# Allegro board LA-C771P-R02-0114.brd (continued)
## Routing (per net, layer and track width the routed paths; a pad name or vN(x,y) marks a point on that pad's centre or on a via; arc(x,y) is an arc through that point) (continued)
DDR_A_ODT2: length 59.6
  IN2 w0.102: 108.21,61.86 108.21,62.72 106.28,64.65 106.28,69.57 106.28,69.64 105.05,70.86 104.45,70.86 v3(103.85,70.26)
  IN2 w0.203: 108.21,61.86 108.21,59.37 113.36,54.21 114.85,54.21 116.25,52.81 116.25,46.77 114.5,45.02 114.5,42.08 114.29,41.86 113.38,41.86 113.1,41.58 113.1,37.4 112.84,37.14 112.33,37.14 112.04,37.43 112.04,39.18 111.81,39.42 111.34,39.42 111.04,39.13 111.04,37.55 110.81,37.32 110.43,37.32 110.22,37.52 110.22,40.62 109.79,41.05 107.4,41.05 106.36,40.01 v3(105.8,40.01)
  BOTTOM w0.102: UC4.P42 v3(103.85,70.26)
  BOTTOM w0.165: JDIMM1.120 105.23,39.44 v3(105.8,40.01)
DDR_A_RAS#: length 44.4
  IN2 w0.102: 104.85,63.21 104.85,64.44 105.26,64.85 105.26,67.22 105.18,67.29 105.18,67.3 104.96,67.52 104.96,67.52 104.95,67.53 104.6,67.53 104.43,67.71 104.43,68.05 104.24,68.23 v3(102.84,68.23)
  IN2 w0.203: v3(102.22,41.25) 101.89,41.25 101.66,41.48 101.66,42.01 101.39,42.29 101.39,42.58 101.59,42.78 102.33,42.78 102.49,42.62 102.49,42.21 102.69,42.01 103.04,42.01 103.3,42.27 103.3,42.97 103.5,43.17 103.85,43.17 104.22,42.8 104.88,42.8 105.09,43.01 105.09,44.62 105.37,44.9 105.37,46.79 106.48,47.9 106.48,53.9 106.76,54.18 107.09,54.18 107.29,53.98 107.29,52.68 107.5,52.47 107.79,52.47 108.1,52.78 108.1,55.14 104.85,58.39 104.85,63.21
  BOTTOM w0.102: UC4.M45 v3(102.84,68.23)
  BOTTOM w0.165: v3(102.22,41.25) 102.23,41.24 JDIMM1.110
DDR_A_RST#: length 81.1
  TOP w0.102: v3(75.32,42.22) 74.71,41.61 74.71,39.81 CD2.1 73.85,38.34 75.01,37.17 v3(75.83,37.17) ; CC20.1 104.08,71.1 v3(103.83,70.85)
  IN2 w0.102: 95.15,76.26 97.44,76.26 98.48,75.22 98.48,74.83 99.86,73.44 101.09,73.44 101.53,73 101.53,72.19 101.65,72.07 102.83,72.07 103.15,71.74 103.15,71.39 103.7,70.85 v3(103.83,70.85)
  IN2 w0.127: v3(75.32,42.22) 75.24,42.3 75.24,45.06 68.36,51.95 68.36,59.44 67.2,60.6 67.2,65.93 77.2,75.92 93.39,75.92 93.72,76.26 95.15,76.26
  BOTTOM w0.102: UC4.P41 v3(103.83,70.85) ; JDIMM1.30 v3(75.83,37.17)
DDR_A_WE#: length 51.4
  IN2 w0.203: v3(104.1,48.16) 104.1,48.19 103.77,48.52 103.43,48.52 103.18,48.27 v3(103.18,45.19)
  BOTTOM w0.102: 97.82,62.36 97.95,62.49 99.96,62.49 101.3,63.83 101.3,64.43 101.36,64.49 101.36,65.46 UC4.H51
  BOTTOM w0.165: v3(104.1,48.16) 103.87,48.39 103.41,48.39 103.08,48.06 101.47,48.06 100.93,48.6 100.93,50.48 101.63,51.17 101.63,53.5 101.44,53.69 101.16,53.69 100.97,53.5 100.97,51.78 100.78,51.58 100.5,51.58 100.31,51.78 100.31,55.37 100.12,55.57 99.84,55.57 99.65,55.37 99.65,48.56 99.46,48.37 99.18,48.37 98.99,48.56 98.99,55.82 96.35,58.46 96.35,60.89 97.82,62.36 ; JDIMM1.113 103.13,45.37 103.18,45.32 v3(103.18,45.19)
DDR_CORE_PWROK: length 61.1
  TOP w0.102: v3(100.54,74.38) 100.4,74.24 92.33,74.24 90.56,76 87.79,76 85.77,78.02 85.77,78.92 85.45,79.24 83.4,79.24 81.77,80.87 81.77,83.02 83.42,84.66 84.92,84.66 86.77,86.52 93.25,86.52 v2(94.13,87.4) 94.65,87.91 v3(94.65,92.72)
  IN2 w0.102: v3(108.69,70.55) 108.69,70.55 108.03,69.88 107.53,69.88 107.36,70.05 107.02,70.39 106.22,70.39 105.31,71.3 105.31,72.9 104.2,74.02 102.77,74.02 102.27,74.53 100.69,74.53 v3(100.54,74.38)
  BOTTOM w0.102: v3(108.69,70.55) 108.69,70.55 108.65,70.54 108.2,70.1 UC4.AB42 ; RC43.2 90.63,93.63 CC21.1 91.72,93.7 UC9.4 94.17,93.7 94.65,93.23 v3(94.65,92.72)
DDR_PWROK: length 81.6
  TOP w0.102: v3(108.69,69.95) 108.14,70.49 108.14,72.01 CC94.1
  TOP w0.254: v3(156.28,28.65) 157.32,28.65 157.61,28.36 v2(157.61,28.1) 157.61,27.97 157.35,27.71 PR406.2
  IN2 w0.127: v3(156.28,28.65) 155.61,29.31 155.61,37.6 154.11,39.1 154.11,41.46 151.01,44.56 145.55,44.56 142.17,47.94 134.05,47.94 119.15,62.84 119.15,64.23 118.49,64.89 117.88,64.89 116.81,65.96 116.81,66.21 116.57,66.45 115.73,66.45 114.73,67.45 114.36,67.45 113.41,68.39 112.26,68.39 112.17,68.3 111.7,68.3 111.14,68.86 111.14,69.54 110.74,69.94 108.69,69.94 v3(108.69,69.95)
  BOTTOM w0.102: UC4.AD42 109.07,69.94 108.69,69.94 v3(108.69,69.95)
  BOTTOM w0.203: v3(156.28,28.65) 155.76,29.16 155.76,30.47 155.58,30.65 PU303.10
DDR_RCOMP0: length 2.9
  TOP w0.254: v3(108.7,69.36) 108.98,69.36 v2(109.35,69.73) 109.35,71.05 RC3.2
  BOTTOM w0.254: UC4.AD44 108.95,69.12 v3(108.7,69.36)
DDR_RCOMP1: length 6.2
  TOP w0.254: RC4.2 112.94,69.86 113.34,69.45 v2(113.34,68.97) 113.34,68.69 112.81,68.16 110.71,68.16 v3(110.6,68.05)
  BOTTOM w0.254: UC4.AF45 110.25,68.41 v3(110.6,68.05)
DDR_RCOMP2: length 4.4
  TOP w0.254: v3(108.76,68.05) 109.1,68.05 109.79,68.74 109.79,70.52 RC5.2
  BOTTOM w0.381: v3(108.76,68.05) 109.12,68.41 UC4.AD45
DDR_TERMN0: length 2.5
  TOP w0.254: v3(110.6,69.47) 110.6,70.25 111.21,70.85 RC1.2
  BOTTOM w0.254: UC4.AF42 110.25,69.83 v3(110.6,69.47)
DDR_TERMN1: length 2.6
  TOP w0.254: v3(111.74,69.47) 112.09,69.81 RC2.2
  BOTTOM w0.254: UC4.AH42 111.1,69.79 111.42,69.47 v3(111.74,69.47)
DEVSLP_SOC: length 1.1
  TOP w0.102: T3.1 116.72,83.85 v3(117.13,84.26)
  BOTTOM w0.102: v3(117.13,84.26) 116.98,84.11 UC4.AY14
DH_CHG: length 1.5
  TOP w0.102: PR217.1 194.09,72.02 v2(194.8,72.73)
  vias: v3(193.35,71.29) v3(194.01,71.28) v3(196.82,71.45) v3(197.42,71.45)
DISPOFF#: length 17.4
  BOTTOM w0.102: JEDP1.10 58.9,97.04 58.38,96.53 54.8,96.53 53.53,95.26 52.61,95.26 51.29,93.94 RX6.2 51.02,94.05 51.02,94.69 v2(50.81,94.9) 50.2,94.9 49.29,93.99 RX8.2 CX14.2 49.28,92.64 RX7.2
DL_CHG: length 4.9
  TOP w0.102: v3(196.69,69.73) v2(196.69,68.84)
  IN2 w1.016: 193.26,66.18 196.12,69.03
  vias: v3(191.68,66.49) v3(191.68,65.85) v3(197.29,69.73)
DRAM_VDD_S4_CLK: length 25.8
  TOP w0.102: v3(122.79,63.89) v2(122.79,63.28)
  TOP w0.381: CC29.1 109.46,71.98 v3(109.65,71.78)
  IN2 w0.254: v3(109.65,71.78) 109.91,72.04 112.32,72.04 112.6,72.32 116.6,72.32 116.82,72.09 118.27,72.09 119.62,70.75 119.62,70.29 120.02,69.88 120.51,69.88 121.11,69.27 121.11,66.22 122.79,64.55 v3(122.79,63.89)
  BOTTOM w0.254: UC4.AF38 110.01,72.14 v3(109.65,71.78) 109.29,72.14 UC4.AD38
  BOTTOM w0.381: RC69.1 121.57,60.49 CC30.1 121.57,62.67 v3(122.79,63.89)
E51RXD_P80CLK: length 243.8
  TOP w0.102: v3(196.92,7.37) 190.83,13.47 175.2,13.47 v2(169.85,18.82) 169.13,19.54 v3(168.8,19.54) ; v3(67.93,24.95) 67.57,24.95 66.13,26.39 UB1.31 ; v3(167.47,82.61) 167.47,83.97 163.42,88.02 154.43,88.02 152.64,89.81 152.64,91.83 152.3,92.16 150.6,92.16 RM12.1
  BOTTOM w0.102: v3(67.93,24.95) 68.18,24.7 69.32,24.7 71.22,22.81 71.22,22.25 72.97,20.49 74.78,20.49 76.37,18.9 79.56,18.9 80.53,19.87 82.06,19.87 83.96,17.97 86.34,17.97 86.82,18.45 90.11,18.45 91.32,17.23 92.66,17.23 93.45,16.44 94.44,16.44 95.25,17.26 101.39,17.26 101.97,16.67 103.42,16.67 104.01,17.26 108.75,17.26 109.77,16.24 114.21,16.24 116.47,13.98 120.14,13.98 126.24,7.88 162.4,7.88 168.8,14.28 v3(168.8,19.54) 168.8,20.75 168.33,21.22 168.33,81.75 v3(167.47,82.61) ; JP1.3 v3(196.92,7.37)
E51TXD_P80DATA: length 242.1
  TOP w0.102: UB1.30 66.53,26.55 67.56,25.51 v3(67.65,25.51) ; v3(167.04,83.02) v2(167.04,83.7) 167.04,84.04 163.29,87.79 154.31,87.79 152.41,89.7 152.41,91.27 RM13.2 RM11.1 ; v3(168.36,20.05) 169.32,20.05 175.67,13.7 190.92,13.7 196.74,7.88 197.37,7.88 v3(197.78,7.46)
  BOTTOM w0.102: v3(167.04,83.02) 167.04,82.2 168.1,81.14 168.1,20.3 v3(168.36,20.05) 168.36,14.16 162.3,8.11 126.55,8.11 120.45,14.2 116.57,14.2 114.31,16.46 109.87,16.46 108.85,17.48 103.91,17.48 103.33,16.9 102.07,16.9 101.48,17.49 95.16,17.49 94.34,16.67 93.55,16.67 92.76,17.46 91.42,17.46 90.2,18.67 87.39,18.67 86.77,19.29 82.96,19.29 82.15,20.1 80.09,20.1 79.28,19.29 76.31,19.29 74.88,20.72 73.07,20.72 71.51,22.27 71.51,22.83 69.41,24.94 68.8,24.94 68.23,25.51 v3(67.65,25.51) ; JP1.2 198.17,7.08 v3(197.78,7.46)
EC_BKOFF#: length 112
  TOP w0.102: v3(74.31,19.97) 75.12,19.16 76.06,19.16 76.54,18.68 76.54,18.07 77.64,16.97 UB1.105 ; v3(44.51,52.73) 44.53,52.73 44.53,52.73 40.53,56.73 40.48,56.73 40.26,56.95 40.26,57 39.73,57.53 39.73,69.62 39.5,69.84 39.5,81.01 44.15,85.66 44.15,88.27 46.16,90.28 47.89,90.28 v3(48.93,91.32)
  IN2 w0.127: v3(74.31,19.97) 73.97,19.63 73.97,18.4 73.11,17.53 71.86,17.53 71.58,17.82 71.58,17.82 71.39,18 71.33,18.06 69.86,18.06 69.05,17.25 64.02,17.25 51.93,29.35 51.93,41.13 50.4,42.66 50.4,51.04 49.41,52.02 45.21,52.02 v3(44.51,52.73)
  BOTTOM w0.102: RX7.1 v3(48.93,91.32)
EC_CLEAR_CMOS: length 6.8
  TOP w0.102: v3(66.68,9.79) 66.93,10.03 UB1.68
  BOTTOM w0.102: v3(66.68,9.79) 65.35,9.79 v2(65.31,9.74) 65.26,9.69 RB31.2 65.54,8.75 66.12,8.16 QB1.2
EC_CS0#: length 35
  TOP w0.102: UB1.128 80.17,26.17 80.33,26.33 80.33,29.1 81.11,29.89 81.11,32.71 78.43,35.39 75.39,35.39 73.67,37.12 69.04,37.12 62.72,43.44 v2(60.54,43.44) RPC8.8
EC_ENVDD: length 97.7
  TOP w0.102: v3(70.16,22.99) 70.89,22.26 70.89,14.84 69.33,13.28 UB1.74 ; v3(76.43,85.93) 76.39,85.98 RX1.1
  IN2 w0.127: v3(62.17,35.95) 62.17,31.61 68.41,25.37 68.41,24.74 v3(70.16,22.99)
  BOTTOM w0.102: v3(76.43,85.93) 69.89,85.93 68.36,84.4 67.76,84.4 67.24,83.88 66.44,83.88 64.3,81.74 64.3,77.31 63.24,76.25 63.24,72.25 66.52,68.97 66.84,68.97 67.4,68.4 67.4,59.31 59.13,51.04 59.13,47.12 56.98,44.96 56.98,40.56 61.59,35.95 v3(62.17,35.95)
EC_KBRST#: length 103.8
  TOP w0.102: UB1.2 77.73,29.83 77.5,30.06 v3(77.5,30.06)
  BOTTOM w0.102: UC4.B18 98.02,82.02 97.61,82.02 96.82,82.81 96.82,82.89 95.91,83.8 95.02,83.8 94.8,84.02 94,84.02 93.17,84.84 90.24,84.84 89.6,85.48 RC36.1 89.49,84.85 89.14,84.5 89.14,84.03 88.76,83.65 86.23,83.65 85.19,82.61 73.61,82.61 72.95,81.95 70.89,81.95 68.11,79.17 68.11,72.14 68.66,71.58 68.66,70.38 69.71,69.33 69.71,58.39 61.43,50.1 61.43,46.13 60.21,44.91 60.21,38.84 62.73,36.32 62.73,35.18 63.89,34.02 64.52,34.02 64.92,33.61 68.87,33.61 71.2,31.28 v2(72.8,31.28) 76.28,31.28 v3(77.5,30.06)
EC_LID_OUT#: length 7.3
  BOTTOM w0.102: RC35.2 93.75,85.48 94.37,84.86 94.37,84.58 v1(94.52,84.42) 94.72,84.22 95.78,84.22 97.09,82.91 97.41,82.91 97.56,82.76 97.83,82.76 98.12,82.48 98.29,82.31 UC4.C17
EC_MUTE#: length 67
  TOP w0.102: v3(72.32,5.39) 72.22,5.49 72.22,7.04 RB12.1 73.94,8.77 73.94,10.29 72.93,11.3 UB1.83 ; RA12.1 31.1,28.46 RA10.2 32.09,28.46 32.79,27.76 33.37,27.76 35.72,25.41 v3(35.72,15.43)
  BOTTOM w0.102: v3(35.72,15.43) 35.72,14.94 37.6,13.06 37.6,10.8 41.82,6.58 59.83,6.58 60.46,5.95 62.72,5.95 63.76,4.91 69.63,4.91 70.62,5.9 71.81,5.9 v3(72.32,5.39)
EC_ON: length 185.1
  TOP w0.203: UB1.112 78.49,19.77 78.18,20.08
  TOP w0.254: v3(104.12,26.58) 104.32,26.37 104.32,13.65 v2(104.68,13.29) 105.21,12.76 v3(105.21,12.4) ; 78.18,20.08 77.28,20.99 74.3,20.99 v3(74.05,21.24)
  IN2 w0.254: v3(104.12,26.58) 103.2,25.66 96.57,25.66 96.31,25.93 93.87,25.93 92.71,27.09 89.47,27.09 88.09,25.71 86.06,25.71 85.2,24.85 81.06,24.85 79.26,23.05 77.75,23.05 76.34,21.65 74.45,21.65 v3(74.05,21.24) ; v3(194.25,43.56) 194.3,43.56 194.95,42.91 201.96,42.91 203.05,41.81 203.05,31.15 179.17,7.27 128.47,7.27 124.28,11.46 110.01,11.46 109.32,12.15 105.47,12.15 v3(105.21,12.4)
  BOTTOM w0.254: PR306.1 v3(194.25,43.56)
EC_RSMRST#: length 135.1
  TOP w0.102: v3(83.03,81.14) 83.03,81.6 82.68,81.94 82.68,83.22 83.16,83.7 CC16.1 RC37.1 84.64,83.7 86.97,86.04 94.85,86.04 v3(95.51,85.38) ; v3(81.01,15.27) 80.7,14.97 UB1.100 ; v3(89.42,16.93) 89.29,17.05 89.29,19.98 88.1,21.16 88.1,26.31 87.23,27.18 87.23,29.25 87.38,29.41 87.38,30.36 v3(87.23,30.51)
  BOTTOM w0.102: v3(87.23,30.51) 84.58,30.51 81.82,33.28 73.6,33.28 73.01,32.69 71.31,32.69 69.65,34.35 65.79,34.35 60.92,39.22 60.92,44.62 62.14,45.83 62.14,49.77 70.43,58.06 70.43,69.62 69.37,70.67 69.37,71.88 68.82,72.43 68.82,76.18 69.69,77.05 69.69,79.75 71.19,81.24 73.24,81.24 73.91,81.9 81.49,81.9 81.79,81.61 82.56,81.61 v3(83.03,81.14) ; UC4.B10 98.22,85.71 95.84,85.71 v3(95.51,85.38) ; v3(81.01,15.27) 81.01,15.68 81.72,16.39 87.16,16.39 87.69,16.93 v3(89.42,16.93)
EC_RST#: length 5
  TOP w0.102: RB10.1 61.82,25.63 CB8.1 61.82,23.65 v2(61.93,23.54) 62.21,23.54 62.31,23.64 62.31,23.98 62.9,24.57 UB1.37
EC_SCI#: length 199.9
  TOP w0.102: v3(118.09,85.24) 118.09,85.17 118.47,84.79 120.3,84.79 121.9,86.39 122.23,86.39 123.32,87.48 v3(123.7,87.48) 123.86,87.33 123.86,85.86 126.02,83.7 126.78,83.7 127.84,82.64 127.84,78.42 129.45,76.82 129.45,63.89 137.7,55.63 140.52,55.63 147.33,48.83 v3(147.33,46.64) ; UB1.20 70.53,30.05 70.01,30.57 RB18.2 70.65,31.3 v3(70.65,32.78) ; v3(106.66,21.05) 106.66,27.57 105.11,29.12 105.11,30.03 v3(102.9,32.24)
  IN2 w0.127: v3(106.66,21.05) 149.67,21.05 152.51,23.88 156.04,23.88 161.22,29.06 161.22,37.73 152.76,46.19 147.78,46.19 v3(147.33,46.64) ; v3(102.9,32.24) 102.79,32.13 96.88,32.13 96.85,32.1 96.51,32.1 96.48,32.13 95.94,32.13 95.89,32.08 95.54,32.08 95.49,32.13 76.19,32.13 75.42,32.9 70.77,32.9 v3(70.65,32.78)
  BOTTOM w0.102: v3(123.7,87.48) 123.83,87.61 124.82,87.61 125.48,88.27 126.02,88.27 127.01,89.26 RC17.2 ; v3(118.09,85.24) 117.69,84.84 UC4.BA12
EC_SCK: length 36.7
  TOP w0.102: UB1.126 80.52,25.37 80.81,25.65 80.81,25.66 80.81,25.67 80.81,28.9 81.62,29.71 v3(81.62,30.11) ; v3(78.8,30.16) 78.8,32.98 78.16,33.62 74.97,33.62 72.99,35.59 68.52,35.59 62.17,41.94 RPC8.5
  BOTTOM w0.102: v3(78.8,30.16) 79.38,30.74 80.96,30.74 81.59,30.11 v3(81.62,30.11)
EC_SDI: length 37.4
  TOP w0.102: UB1.120 78.93,22.97 78.39,23.5 78.39,26.17 79.41,27.19 79.41,29.27 80.04,29.9 80.04,32.42 78.12,34.34 74.93,34.34 73.11,36.15 v2(70.31,36.15) 68.64,36.15 62.35,42.44 RPC8.6
EC_SDIO: length 40.2
  TOP w0.102: UB1.119 78.44,22.57 77.88,23.12 77.88,26.35 78.9,27.36 78.9,29.57 v3(79.54,30.21) ; v3(80.6,30.21) 80.6,32.54 78.31,34.83 75.11,34.83 73.31,36.64 68.84,36.64 v2(67,38.48) 62.54,42.94 RPC8.7
  BOTTOM w0.102: v3(79.54,30.21) v3(80.6,30.21)
EC_SERIRQ: length 186.3
  TOP w0.102: v3(96.68,32.52) 96.68,32.44 101.66,27.46 v3(101.66,20.9) 101.66,18.66 100.87,17.87 100.87,17.05 RW5.2 100,16.87 99.98,16.89 UW2.3 ; v3(146.64,46.57) 146.64,48.73 139.96,55.41 137.61,55.41 129.22,63.8 129.22,76.56 127.54,78.24 127.54,82.43 127.14,82.83 126.12,82.83 124.06,84.9 120.86,84.9 120.25,84.29 v3(120.2,84.29) ; v3(77.25,32.55) RB3.1
  IN2 w0.127: v3(96.68,32.52) 96.25,32.95 95.28,32.95 95.08,32.75 78.9,32.75 78.65,33 77.7,33 v3(77.25,32.55) ; v3(146.64,46.57) 147.2,47.13 152.18,47.13 161.48,37.83 161.48,28.96 156.15,23.63 152.61,23.63 149.45,20.47 106.45,20.47 106.01,20.9 v3(101.66,20.9)
  BOTTOM w0.102: v3(120.2,84.29) 120.69,84.29 UC4.BG13
EC_SERIRQ_R: length 3.9
  TOP w0.102: RB1.2 78.13,30.67 RB3.2 77.25,30.41 77.06,30.23 v2(77.06,29.53) 77.06,29.25 77.33,28.99 UB1.3
EC_SLP_S4#_R2: length 3.6
  TOP w0.102: RB22.2 82.07,24.74 81.49,24.17 v3(81.34,24.17) UB1.123
  BOTTOM w0.102: v2(80.7,24.16) 81.33,24.16 v3(81.34,24.17)
EC_SMB_CK1: length 222.6
  TOP w0.102: RPB1.8 70.21,7.73 70.06,7.87 70.06,9.1 v3(69.88,9.28) 70.06,9.46 70.06,10.75 70.53,11.22 UB1.77
  IN2 w0.127: v3(69.88,9.28) 69.9,9.28 70.32,8.86 70.89,8.86 71.99,9.97 79.06,9.97 80.7,11.6 85.02,11.6 85.54,11.08 88.77,11.08 91.83,8.02 101.53,8.02 101.85,8.34 114.56,8.34 115.22,9 123.31,9 127.58,4.73 181.35,4.73 208.57,31.95 208.57,57.58 206.94,59.2 206.94,65.77 v3(206.66,66.05) 206.66,67.15 206.41,67.4 206.41,82.83 202.73,86.51 202.73,88.34 v3(202.88,88.49)
  BOTTOM w0.102: v3(202.88,88.49) 202.74,88.63 202.74,88.92 PR104.2 ; PR219.1 205.15,67.31 206.41,66.05 v3(206.66,66.05)
EC_SMB_CK1_1: length 5
  BOTTOM w0.102: v1(204.79,66.79) 204.24,67.34 PR219.2 203.23,68.83 203.23,70.24 202.9,70.58 PU1.12
EC_SMB_CK2: length 204.9
  TOP w0.102: RPB1.6 71.21,7.81 71.21,7.89 70.85,8.25 v3(70.85,8.31) 71.33,8.8 RB16.2 ; QC4.1 135.98,82.74 133.01,82.74 132.44,82.17 132.44,62.04 137.85,56.63 140.8,56.63 148.88,48.55 148.88,46.85 v3(149.11,46.62) ; v3(55.28,12.79) 55.13,12.94 55.13,21.45 52.59,23.99 52.59,32.65 56.17,36.23 56.95,36.23 57.41,36.69 61.35,36.69 61.6,36.94 62.09,36.94 63.36,35.67 63.36,35.31 64.02,34.65 v3(64.19,34.65)
  IN2 w0.127: v3(64.19,34.65) 64.32,34.65 65.62,33.36 65.62,32.54 71.4,26.76 76.14,26.76 76.73,27.34 87.66,27.34 88.98,28.66 90.62,28.66 91.35,29.39 95.91,29.39 96.79,28.51 117.82,28.51 130,40.69 v3(130.43,40.69) ; v3(55.28,12.79) 58.55,9.51 60.65,9.51 61.18,8.98 66.78,8.98 67.09,9.28 68.33,9.28 68.89,8.72 69.74,8.72 70.15,8.31 v3(70.85,8.31)
  BOTTOM w0.102: JDIMM1.202 129.83,40.24 130.28,40.69 v3(130.43,40.69) 130.67,40.93 133.23,40.93 137.78,45.47 147.96,45.47 v3(149.11,46.62)
EC_SMB_DA1: length 221
  TOP w0.102: RPB1.7 70.71,7.7 70.37,8.04 70.37,9.15 v3(70.49,9.28) 70.37,9.41 70.37,10.63 70.93,11.19 UB1.78
  IN2 w0.127: v3(202.3,88.49) 202.4,88.38 202.4,86.37 206.08,82.7 206.08,67.06 v3(206.23,66.91) 206.23,65.4 206.51,65.12 206.51,59.16 208.24,57.44 208.24,32.09 181.21,5.06 127.72,5.06 123.45,9.33 115.09,9.33 114.43,8.67 101.71,8.67 101.39,8.35 91.97,8.35 88.91,11.41 85.68,11.41 85.16,11.93 80.56,11.93 78.93,10.3 71.8,10.3 70.79,9.28 v3(70.49,9.28)
  BOTTOM w0.102: PR102.2 202.44,88.94 202.44,88.63 v3(202.3,88.49) ; v3(206.23,66.91) 206.23,67.63 PR218.1
EC_SMB_DA1_1: length 3.5
  BOTTOM w0.102: PU1.11 203,70.98 203.49,70.49 203.49,69.22 204,68.72 PR218.2
EC_SMB_DA2: length 204.5
  TOP w0.102: v3(148.47,46.69) 148.57,46.8 148.57,48.42 140.67,56.32 137.73,56.32 132.14,61.91 132.14,82.3 133.64,83.8 QC5.1 ; v3(64.04,35.29) 64.04,35.42 62.21,37.25 61.48,37.25 61.22,36.99 57.29,36.99 56.83,36.53 56.04,36.53 52.28,32.77 52.28,23.86 54.82,21.32 54.82,12.28 v3(55,12.1) ; RB17.2 72.17,9 v3(71.48,8.31) 71.48,8.11 71.71,7.89 71.71,7.81 71.7,7.81 RPB1.5
  IN2 w0.127: v3(71.48,8.31) 71.06,7.9 70.1,7.9 69.6,8.39 68.76,8.39 68.2,8.95 67.23,8.95 66.92,8.64 61.04,8.64 60.51,9.18 58.27,9.18 55.68,11.76 55.34,12.1 v3(55,12.1) ; v3(130.51,41.43) 130.27,41.43 117.68,28.84 96.93,28.84 96.04,29.72 91.22,29.72 90.48,28.99 88.85,28.99 87.53,27.67 76.59,27.67 76,27.09 71.53,27.09 65.95,32.67 65.95,33.5 64.15,35.29 v3(64.04,35.29)
  BOTTOM w0.102: JDIMM1.200 129.23,40.36 130.31,41.43 v3(130.51,41.43) 130.71,41.23 133.11,41.23 137.65,45.78 147.84,45.78 148.47,46.41 v3(148.47,46.69)
EC_SMB_R_CK2: length 2.2
  TOP w0.102: UB1.79 71.33,10.55 71.33,10.54 RB16.1
EC_SMB_R_DA2: length 4.7
  TOP w0.102: UB1.80 71.73,11.22 72.42,10.53 73.35,10.53 73.55,10.34 v2(73.55,10.13) 73.55,10.02 73.44,9.91 RB17.1
EC_SMCA: length 3.6
  BOTTOM w0.102: JBATT1.3 201.35,91.95 201.95,91.36 202.54,91.36 v2(202.75,91.15) 203.1,90.79 PR104.1
EC_SMDA: length 3.5
  BOTTOM w0.102: JBATT1.4 200.1,91.91 v2(200.79,91.23) 201.81,90.2 PR102.1
EC_WL_OFF#: length 190.9
  TOP w0.102: v3(169.1,85.71) 169.1,86.32 165.01,90.41 RM5.2 ; UB1.72 68.53,13.32 v3(70.14,14.93) ; v3(108.59,16.06) 108.59,16.06 v3(110.17,17.63)
  IN2 w0.127: v3(70.14,14.93) 70.61,14.46 75.78,14.46 77.13,15.81 78.2,15.81 79.16,16.77 83.74,16.77 84.26,16.25 91.64,16.25 93.8,14.09 102.94,14.09 104.65,15.81 108.34,15.81 v3(108.59,16.06)
  BOTTOM w0.102: v3(110.17,17.63) 111.1,16.69 114.4,16.69 116.15,14.94 v2(119.36,14.94) 120.2,14.94 126.67,8.47 162.34,8.47 167.62,13.75 167.62,81.25 166.5,82.37 166.5,83.52 168.69,85.71 v3(169.1,85.71)
ECAGND: length 189.3
  TOP w0.203: 67.55,9.53 67.69,9.67 67.69,10.58 67.33,10.94 UB1.69 67.33,13.55 ; v3(85.83,21.04) 85.83,20.47 87.18,19.12 87.18,18.14 PR113.1
  TOP w0.254: 67.33,13.55 67.33,13.65 70.26,16.59 v3(70.26,17.05) ; 67.55,9.53 CB2.2 67.16,8.27 CB1.2 67.17,7.49 L4.2 ; v3(145.3,46.72) 143.76,48.26 143.76,49.54 139.19,54.11 136.94,54.11 128.13,62.92 128.13,74.74 127.09,75.78 124.32,75.78 123.3,76.79 123.3,77.58 122.84,78.04 122.11,78.04 121.72,77.65 119.01,77.65 PH100.2
  IN2 w0.203: v3(145.3,46.72) 146.4,45.61 152.53,45.61 160.05,38.09 160.05,28.71 155.82,24.47 152.1,24.47 149.25,21.62 100.65,21.62 100.27,21.24 99.17,21.24 98.7,21.24 97.63,22.31 92.58,22.31 92.17,22.72 88.26,22.72 86.63,21.09 85.89,21.09 v3(85.83,21.04) 85.53,20.74 84.69,20.74 84.34,21.09 78.54,21.09 76.82,19.36 75.68,19.36 74.92,18.61 74.92,18.53 74.93,18.53 74.93,18 73.46,16.54 71.51,16.54 71,17.05 v3(70.26,17.05)
EDP_AUXN: length 71.9
  IN2 w0.127: v3(86.75,92.23) 86.99,91.99 86.99,91.64 85.82,90.47 85.82,88.38 83.73,86.29 78.71,86.29 78.21,86.78 73.07,86.78 72.06,87.8 68.03,87.8 61.55,87.8 60.38,88.96 60.38,90.38 59.97,90.79 58.58,90.79 58.31,90.52 58.31,90.19 58.14,90.02 v3(57.74,90.02)
  BOTTOM w0.102: v3(57.74,90.02) CX3.1 ; v3(86.75,92.23) 86.98,92.45 86.98,92.67 86.25,93.39 86.25,94.87 90.06,98.67 101.83,98.67 104.21,96.29 105.56,96.29 108.8,93.05 109.74,93.05 111.03,91.76 111.16,91.76 112.09,90.82 112.09,89.89 UC4.AK2
EDP_AUXN_C: length 5.6
  BOTTOM w0.102: RX2.2 58.27,89.82 58.27,91.05 CX3.2 58.29,92.12 58.29,93.19 57.9,93.58 JEDP1.7
EDP_AUXP: length 71.8
  IN2 w0.127: v3(59.01,90.03) 58.77,90.03 58.58,90.21 58.58,90.41 58.69,90.52 59.86,90.52 60.12,90.27 60.12,88.85 61.44,87.53 68.14,87.53 71.95,87.53 72.96,86.52 78.1,86.52 78.6,86.02 83.84,86.02 86.09,88.27 86.09,90.36 87.26,91.53 87.26,91.99 v3(87.49,92.23)
  BOTTOM w0.102: v3(59.01,90.03) CX4.1 ; v3(87.49,92.23) 87.19,92.53 87.19,92.76 86.47,93.48 86.47,94.78 90.15,98.46 101.74,98.46 104.12,96.07 105.47,96.07 108.71,92.83 109.65,92.83 110.94,91.54 111.07,91.54 111.88,90.73 111.88,90.1 111.85,90.07 111.77,89.99 111.77,89.77 111.88,89.66 UC4.AK3
EDP_AUXP_C: length 5.7
  BOTTOM w0.102: RX4.1 58.48,89.79 58.48,91.05 CX4.2 58.5,92.07 58.5,93.15 58.9,93.54 JEDP1.9
EDP_HPD#: length 70.5
  TOP w0.102: v3(102.24,75.5) 102.24,75.44 101.43,74.62 101.43,74.36 100.83,73.77 98.3,73.77 97.65,73.12 97.02,73.12 96.86,73.29 88.09,73.29 85.13,76.24 84.39,76.24 83.78,76.84 83.53,76.84 83.08,77.3 83.08,77.64 81.85,78.87 81.85,79.64 81.5,79.98 80.79,79.98 v3(80.37,79.57) v1(80.37,78.89) 81.16,78.1 CC5.2
  IN1 w0.127: v3(52.32,81.27) 52.38,81.34 52.38,85.45 49.82,88.01 49.82,88.02 49.53,88.3 v3(49.18,88.3)
  IN2 w0.127: v3(80.37,79.57) 79.05,79.57 78.62,79.99 75.41,79.99 74.86,80.54 62.53,80.54 61.79,81.28 61.05,81.28 59.95,82.38 53.42,82.38 v3(52.32,81.27)
  BOTTOM w0.102: UC4.K30 102.24,75.93 v3(102.24,75.5) ; QX1.1 49.84,89.79 RX3.2 49.84,89 49.18,88.34 v3(49.18,88.3)
EDP_HPD_CONN: length 14.6
  BOTTOM w0.102: JEDP1.12 59.9,99.72 59.27,99.09 59.27,97.09 58.33,96.15 54.74,96.15 53.47,94.88 53.05,94.88 CX15.2 52.03,92.98 RX5.1 52.7,92.31 QX1.2
EDP_TXN0: length 65.5
  IN2 w0.127: v3(87.27,93.67) 87.27,93.87 87.13,94.01 86.89,94.01 85.31,92.44 85.31,88.7 83.41,86.8 79.03,86.8 78.17,87.66 73.11,87.66 72.46,88.31 67.82,88.31 63.27,88.31 62.68,88.9 62.68,90.02 62.2,90.5 61.62,90.5 61.39,90.26 61.39,89.97 61.53,89.82 v3(61.95,89.82)
  BOTTOM w0.102: UC4.AG1 110.69,90.33 110.69,90.77 110.27,91.19 109.48,91.98 108.55,91.98 105.15,95.37 103.8,95.37 101.52,97.66 101.42,97.76 90.57,97.76 88.07,95.26 88.07,94.42 87.66,94.01 87.37,94.01 87.27,93.91 v3(87.27,93.67) ; CX6.1 61.45,90.68 61.37,90.6 61.37,89.99 61.54,89.82 v3(61.95,89.82)
EDP_TXN0_C: length 2.8
  BOTTOM w0.102: CX6.2 61.5,91.97 61.5,93.2 61.9,93.6 JEDP1.15
EDP_TXN1: length 63.3
  IN2 w0.127: v3(65.09,89.71) 64.55,89.71 64.47,89.79 64.47,90.28 64.62,90.43 65.14,90.43 66.37,89.2 73.46,89.2 73.63,89.03 73.63,88.72 73.49,88.58 v3(73.31,88.58)
  BOTTOM w0.102: UC4.AF2 110.05,89.96 110.05,90.34 109.92,90.47 109.2,91.19 108.32,91.19 104.94,94.57 103.41,94.57 101.05,96.93 100.92,97.06 90.94,97.06 88.78,94.9 88.78,91.83 87.04,90.09 87.04,88.06 84.15,85.17 80.05,85.17 79.62,85.59 79.13,85.59 77.6,87.13 77.07,87.13 77.07,87.13 74.48,87.13 73.63,87.98 73.63,88.42 73.47,88.58 v3(73.31,88.58) ; v3(65.09,89.71) 64.6,89.71 64.41,89.9 64.41,90.61 64.48,90.68 CX8.1
EDP_TXN1_C: length 2.9
  BOTTOM w0.102: JEDP1.21 64.9,93.47 64.5,93.08 64.5,92.02 CX8.2
EDP_TXP0: length 65.5
  IN2 w0.127: v3(87.27,94.42) 87.13,94.28 86.78,94.28 85.05,92.55 85.05,88.81 83.3,87.06 79.14,87.06 78.28,87.93 73.22,87.93 72.58,88.58 67.71,88.58 67.71,88.57 63.38,88.57 62.95,89.01 62.95,90.13 62.31,90.76 61.51,90.76 61.12,90.37 61.12,89.95 v3(60.99,89.82)
  BOTTOM w0.102: CX5.1 61.15,90.4 61.15,89.98 v3(60.99,89.82) ; v3(87.27,94.42) 87.47,94.22 87.57,94.22 87.85,94.51 87.85,95.35 90.48,97.97 101.51,97.97 101.67,97.81 103.89,95.59 105.24,95.59 108.64,92.19 109.57,92.19 110.42,91.34 110.57,91.19 110.9,90.86 110.9,90.09 110.82,90 UC4.AG3
EDP_TXP0_C: length 2.9
  BOTTOM w0.102: JEDP1.13 60.9,93.62 61.29,93.23 61.29,92.02 CX5.2
EDP_TXP1: length 63.3
  IN2 w0.127: v3(64.06,89.69) 64.2,89.83 64.2,90.39 64.51,90.7 65.25,90.7 66.48,89.46 73.57,89.46 73.9,89.14 73.9,88.67 v3(74.02,88.55)
  BOTTOM w0.102: CX7.1 64.19,90.4 64.19,89.83 v3(64.06,89.69) ; v3(74.02,88.55) 73.84,88.38 73.84,88.07 74.57,87.35 77.17,87.35 77.17,87.34 77.69,87.34 79.22,85.81 79.71,85.81 80.14,85.38 84.06,85.38 86.82,88.15 86.82,90.18 88.56,91.92 88.56,94.99 90.85,97.27 101.01,97.27 103.5,94.79 105.03,94.79 108.41,91.41 109.29,91.41 110.08,90.62 110.27,90.43 110.27,90.17 110.43,90.01 110.43,89.75 110.29,89.6 UC4.AF3
EDP_TXP1_C: length 2.8
  BOTTOM w0.102: CX7.2 64.29,91.97 64.29,93.08 63.9,93.47 JEDP1.19
EN_0.675VSP: length 4.4
  TOP w0.254: v3(156.5,32.65) 156.5,32.55 155.9,31.95 PC419.1 154.66,32.86 PR411.2
  BOTTOM w0.203: PU303.7 155.8,31.85 156.5,32.55 v3(156.5,32.65)
EN_DDR: length 4.7
  TOP w0.102: v2(157.11,32.01) 157.11,31.99 v3(156.55,31.44)
  TOP w0.254: PR410.2 154.66,30.14 PC418.1 155.96,31.44 v3(156.55,31.44)
  BOTTOM w0.203: PU303.8 156.54,31.45 v3(156.55,31.44)
ENLDO_3V5V: length 8.2
  TOP w0.102: v3(189.1,39.62) v2(189.1,38.92)
  IN1 w0.254: v3(188.27,43.6) 188.27,40.45 v3(189.1,39.62)
  BOTTOM w0.254: v3(188.27,43.6) 188.6,43.6 188.84,43.36 PR303.1 PR301.1 ; PU301.7 189.18,39.55 v3(189.1,39.62)
ENVDD: length 50.4
  TOP w0.102: RPC1.6 79.45,75.59 79.15,75.29 79.15,74.62 78.3,73.77 78.3,73.36 73.77,68.83 67.86,68.83 67.74,68.94 65.71,68.94 64.99,69.67 63.74,69.67 62.13,71.27 62.13,78.14 v3(61.94,78.34) ; v3(62.91,81.06) 62.91,83.46 v2(63.38,83.93) 64.05,84.6 71.06,84.6 71.78,83.89 73.85,83.89 UX1.4 75.03,85.07 RX1.2
  IN1 w0.127: v3(62.91,81.06) 62.91,79.31 v3(61.94,78.34)
  BOTTOM w0.102: v3(61.94,78.34) 61.16,78.34 RC12.2
EXT_MIC_RING2: length 2.2
  TOP w0.203: v2(20.58,26.6) 21.01,26.17 21.01,25.36 21.3,25.08 UA1.17
EXT_MIC_SLEEVE: length 3.3
  TOP w0.203: UA1.18 21.16,24.68 20.86,24.98 v2(20.61,24.98) 20.35,24.98 20.1,24.72 20.1,24.39 RA17.1
FB_1.05V: length 4.5
  TOP w0.102: PC503.2 56.71,59.23 v2(56.26,59.68)
  TOP w0.254: PU501.1 60,59.23 PR506.1 PR505.2 PC503.2
FB_DDR: length 4.9
  BOTTOM w0.102: v2(156.6,36.1) 155.92,35.43 PR409.1
  BOTTOM w0.203: PU303.6 155.55,32.25 155.7,32.4 155.7,34.44 PR407.1 155.59,35.41 PR409.1
GPIO_NC12: length 2.7
  BOTTOM w0.102: UC4.B30 98.19,75.96 97.51,75.96 97.42,76.06 97.05,76.06 96.44,75.45 T2.1
GPIO_NC13: length 6.6
  BOTTOM w0.102: RC14.2 RC15.1 v2(93.45,75.83) 93.48,75.83 93.77,76.11 96.46,76.11 96.81,76.47 97.83,76.47 UC4.A29
GPIO_NC14: length 4.7
  BOTTOM w0.102: UC4.C29 98.47,76.37 98.17,76.37 97.99,76.19 97.62,76.19 97.54,76.27 96.9,76.27 96.53,75.9 95.1,75.9 94.57,75.38 T1.1
GPIO_RCOMP: length 1.2
  TOP w0.381: v3(103.43,78.38) 103.48,78.38 RC44.2
  BOTTOM w0.254: v3(103.43,78.38) 103.74,78.06 UC4.N26
GPIO_S0_SC_56: length 15.2
  TOP w0.102: RC63.1 126.04,95.13 126.02,95.11 RC58.2 126.02,93.48 v2(125.52,92.99) 123.27,90.74 123.27,89.37 122.54,88.63 122.54,88.37 121.7,87.53 121.7,87.13 120.27,85.7 119.13,85.7 118.78,85.36 v3(118.78,85.19)
  BOTTOM w0.102: UC4.BC12 118.78,85.15 v3(118.78,85.19)
GPIO_S0_SC_63: length 4.5
  TOP w0.102: RC21.2 120,75.95 118.58,75.95 v3(118.05,76.48) 117.91,76.48 117.42,75.99 v1(117.27,75.99)
  BOTTOM w0.102: UC4.BA30 117.69,76.12 v3(118.05,76.48)
GPIO_S0_SC_65: length 11.6
  BOTTOM w0.102: UC4.BC30 118.84,75.56 119.1,75.56 119.45,75.22 119.45,74.88 119.69,74.64 120.28,74.64 120.44,74.71 120.53,74.76 120.6,74.83 120.84,74.83 121.01,74.66 121.01,74.65 121.1,74.57 121.1,74.46 121.44,74.11 122.45,74.11 123.41,73.16 123.83,73.16 124.46,73.79 RC22.2 124.6,73.79 124.6,72.91 RC23.2 124.37,72.68 123.65,72.68 123.55,72.58 v2(123.55,72.17) 123.55,71.68 QC1.1
GPIO_S0_SC_92: length 3.1
  BOTTOM w0.102: T18.1 123.58,74.93 122.33,76.18 121.27,76.18 UC4.BH30
GPIO_S0_SC_93: length 5.1
  BOTTOM w0.102: UC4.BG30 120.67,75.99 120.98,75.67 121.18,75.67 121.46,75.95 122.23,75.95 122.87,75.32 122.87,74.28 T19.1
GPIO_S5_14: length 8.8
  TOP w0.102: v3(101.2,80.36) 100.73,79.88 100.42,79.88 100.26,79.73 100.26,79.1 99.98,78.83 98.43,78.83 v2(97.89,78.28) 97.89,76.27 98.24,75.92 98.6,75.92 98.78,76.1 RPC5.3
  BOTTOM w0.102: v3(101.2,80.36) 101.61,80.77 UC4.J20
GPIO_S5_17: length 1.3
  TOP w0.102: v3(101.35,79.4) 101.35,79.06 T8.1
  BOTTOM w0.102: v3(101.35,79.4) 101.35,79.16 UC4.J24
H_PROCHOT#: length 131
  TOP w0.102: v3(97.16,20.73) 97.16,20.73 97.16,20.76 97.06,20.86 97.06,24.9 96.3,25.66 96.3,29.19 v3(94.67,30.82) ; RB26.2 82.65,16.92 RB24.2 82.58,17.15 82.96,17.53 84.08,17.53 v3(85.38,18.83)
  IN2 w0.127: v3(85.38,18.83) 86.28,19.73 87.01,19.73 87.64,20.35 95.82,20.35 96.1,20.08 96.81,20.08 97.16,20.42 v3(97.16,20.73)
  BOTTOM w0.102: UC4.C24 98.76,78.74 98.48,78.74 98.31,78.57 98.13,78.57 98.08,78.61 98,78.7 97.68,78.7 97.67,78.7 97.66,78.7 97.5,78.54 95.26,78.54 95.15,78.43 94.46,78.43 93.7,79.19 93.45,79.19 RC20.1 92.73,79.91 92.73,80.13 92.36,80.49 91.68,80.49 91.48,80.3 CB12.1 90.75,80.3 90.26,79.82 89.29,79.82 89.11,80 88.43,80 v1(86.13,77.7) 85.69,77.25 75.94,77.25 74.26,75.58 74.26,74.85 74.79,74.33 74.79,56.23 66.47,47.91 66.47,46.5 65.54,45.57 65.54,44.49 64.28,43.23 64.28,41.89 65.64,40.52 65.64,38.95 67.37,37.22 71.06,37.22 71.92,36.36 83.78,36.36 85.61,34.52 87.75,34.52 89.67,32.6 92.89,32.6 v3(94.67,30.82)
HDA_BIT_CLK: length 7.5
  TOP w0.102: v2(124.19,80.68) 124.19,79.64 v3(123.27,78.72)
  BOTTOM w0.102: UC4.BJ21 121.5,80.37 121.86,80.01 122.09,80.01 123.27,78.82 v3(123.27,78.72) 123.27,78.37 124.28,77.37 RPC4.6
HDA_BITCLK_AUDIO: length 219.9
  TOP w0.102: UA1.6 24.97,28.08 25.55,28.66 26.17,28.66 27.34,29.83 27.34,32.4 RA11.1 26.23,32.59 v3(25.69,33.13)
  BOTTOM w0.102: v3(25.69,33.13) 25.94,33.38 34.65,33.38 37.98,30.05 60.41,30.05 62.98,27.49 74.76,27.49 75.5,28.23 90.15,28.23 90.91,28.99 100.87,28.99 102.32,27.54 104.47,27.54 104.93,27.09 121.35,27.09 126.74,21.7 154.28,21.7 158.3,25.72 158.3,38.79 149.25,47.84 140.62,47.84 v2(132.8,55.65) 128.02,60.43 128.02,63.88 127.51,64.39 127.51,67.9 128.91,69.3 128.91,71.92 127.71,73.12 127.71,74.94 126.82,75.84 126.82,77.01 126.46,77.37 RPC4.3
HDA_RCOMP: length 5.7
  BOTTOM w0.089: 120.76,81.04 120.59,81.04 120.5,81.14 120.09,81.14 UC4.BF20
  BOTTOM w0.102: 120.76,81.04 120.84,81.04 120.85,81.06 120.86,81.06 120.94,81.13 120.95,81.13 120.96,81.14 121.2,81.14 121.29,81.06 121.83,81.06 122.24,80.65 123.23,80.65 123.46,80.42
  BOTTOM w0.254: RC19.1 124.29,79.6 v2(123.76,80.13) 123.46,80.42
HDA_RST#: length 7.1
  TOP w0.102: v2(123.82,78.09) 123.99,77.92 123.99,77.12 v3(124.01,77.09)
  BOTTOM w0.102: UC4.BG22 120.66,79.88 121.11,79.43 121.11,79.31 121.81,78.61 121.91,78.61 123.42,77.09 v3(124.01,77.09) 124.62,77.09 124.85,76.87 RPC4.5
HDA_RST_AUDIO#: length 218.7
  TOP w0.102: v3(22.92,32.57) 22.51,32.16 22.51,28.36 22.97,27.89 UA1.11
  BOTTOM w0.102: v3(22.92,32.57) 24.21,33.87 34.85,33.87 38.18,30.54 60.61,30.54 63.18,27.97 74.56,27.97 75.3,28.71 87.85,28.71 87.93,28.8 90.04,28.8 90.71,29.47 101.07,29.47 102.52,28.03 106.41,28.03 106.87,27.57 121.55,27.57 126.94,22.18 154.08,22.18 157.82,25.92 157.82,37.39 157.25,37.96 157.25,39.16 149.05,47.35 140.42,47.35 v2(130.3,57.47) 127.54,60.23 127.54,63.68 126.98,64.24 126.98,68.05 128.43,69.5 128.43,71.72 127.23,72.92 127.23,74.74 126.26,75.71 RPC4.4
HDA_SDIN0: length 10.1
  BOTTOM w0.102: UC4.BG19 120.86,81.48 121.16,81.48 121.3,81.62 122.92,81.62 123.21,81.33 123.21,81.33 124.51,80.03 126.43,80.03 v2(126.89,79.57) 126.95,79.51 126.95,78.92 128.51,77.37 RA13.2
HDA_SDIN0_AUDIO: length 218
  TOP w0.102: UA1.8 24.17,28.29 24.3,28.42 24.3,28.93 24.62,29.24 25.13,29.24 25.86,29.98 v3(25.86,31.17)
  BOTTOM w0.102: v3(25.86,31.17) 28.6,31.17 29.37,31.94 34.05,31.94 37.38,28.61 56.09,28.61 56.55,28.15 59.49,28.15 60.63,27.02 61.4,27.02 62.38,26.04 75.36,26.04 76.1,26.78 87.05,26.78 87.87,25.96 95.2,25.96 96.78,27.54 99.78,27.54 101.68,25.64 120.75,25.64 126.14,20.25 154.88,20.25 159.75,25.12 159.75,39.39 149.85,49.28 142.52,49.28 v2(140.95,50.86) 136.02,55.78 134.72,55.78 129.47,61.03 129.47,64.48 128.96,64.99 128.96,67.3 130.36,68.7 130.36,72.52 129.16,73.72 129.16,75.68 RA13.1
HDA_SDOUT: length 7.6
  TOP w0.102: v2(125.2,79.28) 124.95,79.28 v3(124.26,78.6)
  BOTTOM w0.102: UC4.BG20 120.57,80.66 120.86,80.66 120.96,80.56 121.2,80.56 121.29,80.65 121.62,80.65 122.03,80.24 122.26,80.24 123.41,79.09 123.84,79.09 124.26,78.67 v3(124.26,78.6) 124.26,78.09 124.48,77.87 RPC4.7
HDA_SDOUT_AUDIO: length 216.6
  TOP w0.102: UA1.5 25.37,28.09 25.46,28.18 26.37,28.18 27.97,29.78 27.97,30.72 28.67,31.42 28.82,31.42 30.31,32.9 v3(30.31,32.9)
  BOTTOM w0.102: RPC4.2 126.64,77.87 127.3,77.21 127.3,76.04 128.2,75.14 128.2,73.32 129.4,72.12 129.4,69.1 128,67.7 128,64.59 128.51,64.08 128.51,60.63 134.32,54.82 v2(135.39,54.82) 135.62,54.82 142.12,48.32 149.45,48.32 158.78,38.99 158.78,25.52 154.48,21.22 126.54,21.22 121.15,26.6 104.73,26.6 104.27,27.06 101.84,27.06 100.39,28.5 96.38,28.5 95.62,27.75 75.7,27.75 74.96,27.01 62.78,27.01 60.21,29.57 37.78,29.57 34.45,32.9 v3(30.31,32.9)
HDA_SPKR: length 277.4
  IN1 w0.127: v3(168.81,77.89) 168.81,78.41 161.53,85.7 153.01,85.7 152.46,86.24 134.3,86.24 v3(133.62,86.91)
  BOTTOM w0.102: CA32.1 24.94,30.59 28.71,30.59 29.57,31.45 33.76,31.45 37.18,28.03 55.98,28.03 57.48,26.54 61.2,26.54 61.89,25.84 61.89,25.46 62.6,24.74 65.54,24.74 67.98,22.31 69.6,22.31 72.9,19.01 73.62,19.01 75.19,17.43 78.77,17.43 80.73,19.39 81.86,19.39 83.76,17.48 86.55,17.48 87.02,17.96 89.91,17.96 91.12,16.75 92.46,16.75 93.25,15.96 94.64,15.96 95.45,16.78 100.54,16.78 101.68,15.63 113.39,15.63 115.86,13.16 v2(118.02,13.16) 120.27,13.16 126.04,7.4 162.6,7.4 169.28,14.08 169.28,21.08 168.81,21.55 v3(168.81,77.89) ; v3(133.62,86.91) 132.62,85.91 124.51,85.91 124.01,85.41 123.2,85.41 122.48,84.69 121.13,84.69 UC4.BH12
HDA_SYNC: length 5.8
  TOP w0.102: v2(122.74,79.64) 123.38,79.64 v3(123.4,79.66)
  BOTTOM w0.102: UC4.BH20 121.08,80.85 121.75,80.85 122.15,80.45 122.61,80.45 v3(123.4,79.66) 123.78,79.66 124.71,78.73 124.71,78.6 124.93,78.37 RPC4.8
HDA_SYNC_AUDIO: length 221.9
  TOP w0.102: UA1.10 23.37,27.98 23.02,28.33 v3(23.02,31.3)
  BOTTOM w0.102: RPC4.1 126.82,78.37 127.78,77.41 127.78,76.24 128.68,75.34 128.68,73.52 129.88,72.32 129.88,68.9 128.48,67.5 128.48,64.79 128.99,64.28 128.99,60.83 134.52,55.3 135.82,55.3 v2(138.28,52.84) 142.32,48.8 149.65,48.8 159.26,39.19 159.26,25.32 154.68,20.74 126.34,20.74 120.95,26.12 102.09,26.12 100.19,28.02 96.58,28.02 95.82,27.26 75.9,27.26 75.16,26.52 62.58,26.52 61.58,27.51 61.26,27.51 61.25,27.5 60.91,27.5 60.9,27.51 60.81,27.51 59.69,28.63 56.75,28.63 56.29,29.09 37.58,29.09 34.25,32.42 25.05,32.42 23.93,31.3 v3(23.02,31.3)
HDMI_C_CLK+: length 5.7
  TOP w0.102: RY9.1 19.37,86.75 v4(20.48,86.75) 21.85,86.75 v3(22.03,86.92)
  BOTTOM w0.102: LY1.1 21.42,86.9 21.6,86.72 21.83,86.72 22.03,86.92 ; 22.03,86.92 v3(22.03,86.92) ; 22.03,86.92 22.23,86.72 22.85,86.72 CY8.1
HDMI_C_CLK-: length 5.7
  TOP w0.102: v3(22.05,86.34) 21.86,86.53 20.76,86.53 20.75,86.52 20.22,86.52 20.2,86.53 19.35,86.53 RY7.1
  BOTTOM w0.102: CY7.1 22.88,86.51 22.22,86.51 v3(22.05,86.34) 21.88,86.51 21.59,86.51 21.47,86.4 LY1.4
HDMI_C_TX0+: length 5.7
  TOP w0.102: v3(22.23,82.17) 22.02,82.39 21,82.39 20.98,82.37 20.45,82.37 20.44,82.39 19.29,82.39 RY8.1
  BOTTOM w0.102: LY2.4 21.69,82.22 21.86,82.39 22.02,82.39 v3(22.23,82.17) 22.4,82.34 22.78,82.34 23.13,82 CY6.1
HDMI_C_TX0-: length 5.7
  TOP w0.102: RY6.1 19.29,82.6 v4(20.72,82.6) 22.05,82.6 v3(22.23,82.78)
  BOTTOM w0.102: LY2.1 21.77,82.72 21.88,82.6 22.05,82.6 v3(22.23,82.78) 22.46,82.56 22.74,82.56 CY5.1
HDMI_C_TX1+: length 5.7
  TOP w0.102: v3(22.03,84.99) 21.85,84.81 v4(20.47,84.81) 19.36,84.81 RY3.1
  BOTTOM w0.102: CY2.1 22.83,84.8 22.22,84.8 v3(22.03,84.99) 21.83,84.8 21.64,84.8 21.47,84.96 LY3.1
HDMI_C_TX1-: length 5.7
  TOP w0.102: RY1.1 19.35,84.6 20.19,84.6 20.21,84.59 20.74,84.59 20.75,84.6 21.81,84.6 v3(22.03,84.38)
  BOTTOM w0.102: CY1.1 22.89,84.59 22.23,84.59 v3(22.03,84.38) 21.83,84.58 21.61,84.58 21.49,84.46 LY3.4
HDMI_C_TX2+: length 5.7
  TOP w0.102: RY5.1 19.24,80.43 v4(20.64,80.43) 21.97,80.43 v3(22.15,80.24)
  BOTTOM w0.102: CY4.1 22.75,80.45 22.36,80.45 v3(22.15,80.24) 21.95,80.45 21.84,80.45 21.69,80.31 LY4.4
HDMI_C_TX2-: length 5.7
  TOP w0.102: RY4.1 19.35,80.65 20.37,80.65 20.38,80.66 20.91,80.66 20.92,80.65 21.9,80.65 v3(22.13,80.88)
  BOTTOM w0.102: LY4.1 21.65,80.81 21.79,80.67 21.92,80.67 v3(22.13,80.88) 22.34,80.67 22.81,80.67 CY3.1
HDMI_CLK+: length 105.7
  IN2 w0.127: v3(25.9,87.95) 25.9,87.7 25.79,87.59 25.61,87.59 25.31,87.89 25.31,89.29 29.75,93.73 36.7,93.73 40.79,97.82 67.83,97.82 68.34,98.33 69.94,98.33 70.58,97.68 84.57,97.68 86.04,99.15 101.02,99.15 105.83,94.34 111.49,94.34 111.81,94.66 112.02,94.66 v3(112.21,94.47)
  BOTTOM w0.102: v3(25.9,87.95) 25.55,87.6 25.36,87.6 25,87.25 25,86.9 24.85,86.75 24.44,86.75 CY8.2 ; v3(112.21,94.47) 112.21,94.71 112.28,94.78 112.61,94.78 112.72,94.66 112.72,91.56 113.86,90.42 113.86,90.13 113.71,89.98 113.71,89.76 113.89,89.58 UC4.AP3
HDMI_CLK-: length 105.7
  IN2 w0.127: v3(25.9,87.13) 25.71,87.32 25.5,87.32 25.04,87.78 25.04,89.4 29.64,94 36.59,94 40.68,98.09 67.72,98.09 68.23,98.6 70.05,98.6 70.69,97.95 84.46,97.95 85.93,99.42 101.13,99.42 105.94,94.61 111.38,94.61 111.7,94.93 112,94.93 v3(112.26,95.19)
  BOTTOM w0.102: CY7.2 24.46,86.53 24.94,86.53 25.22,86.81 25.22,87.16 25.45,87.38 25.65,87.38 v3(25.9,87.13) ; v3(112.26,95.19) 112.46,94.99 112.7,94.99 112.93,94.75 112.93,91.65 114.08,90.51 114.08,89.93 UC4.AP2
HDMI_DDCCLK: length 106.3
  TOP w0.102: QY2.3 v3(20.55,94.3)
  IN2 w0.127: v3(75.59,76.28) 74.49,76.28 73.77,77 71.53,77 70.58,77.95 64.19,77.95 63.34,77.09 56.72,77.09 56.13,76.5 56.13,75.9 56.39,75.64 v3(56.39,75.17)
  BOTTOM w0.102: RPY1.6 18.05,88.79 18.22,88.96 19.11,88.96 19.56,89.42 19.56,93.32 v3(20.55,94.3) 23.54,94.3 24.24,93.61 27.47,93.61 29.5,91.58 29.5,90.98 29.5,90.98 29.5,90.64 29.81,90.33 29.81,88.15 30.36,87.61 30.36,79.68 35.43,74.61 39.64,74.61 39.95,74.3 44.39,74.3 45.12,73.57 50.58,73.57 52.66,75.65 55.9,75.65 v3(56.39,75.17) ; v3(75.59,76.28) 83.64,76.28 v2(83.65,76.29) 89.91,76.29 90.46,76.84 92.84,76.84 92.89,76.88 96.4,76.88 96.63,77.12 97.95,77.12 98.12,77.28 98.32,77.28 98.5,77.1 98.8,77.1 UC4.C28
HDMI_DDCDATA: length 102.6
  TOP w0.102: QY3.3 v3(20.52,91.92)
  IN2 w0.127: v3(76.03,76.77) 76.01,76.8 74.69,76.8 73.97,77.52 71.73,77.52 70.62,78.62 63,78.62 62.87,78.76 57.34,78.76 55.58,77 55.58,75.28 v3(55.79,75.08)
  BOTTOM w0.102: RPY1.5 19.28,88.44 20.05,89.22 20.05,91.44 v3(20.52,91.92) 26.96,91.92 28.96,89.91 28.96,89.3 29.33,88.93 29.33,87.95 29.83,87.46 29.83,79.53 35.23,74.13 39.44,74.13 39.75,73.81 44.19,73.81 44.92,73.08 50.78,73.08 52.77,75.08 v3(55.79,75.08) ; UC4.C26 98.64,77.93 98.32,77.6 98.12,77.6 97.98,77.75 96.04,77.75 95.67,77.38 90.17,77.38 89.56,76.77 v2(79.23,76.77) v3(76.03,76.77)
HDMI_GND: length 18.7
  TOP w0.508: QY1.3 16.55,94.84 17.24,94.15 17.24,92.38 17.1,92.23 17.1,92.22 16.75,91.88 16.75,91.34 15.59,90.18 15.43,90.18 14.76,89.52 14.76,88.87 15.98,87.66 v2(16.75,87.66) 17.54,87.66 RY9.2 18.05,86.14 RY7.2 RY3.2 RY1.2 RY6.2 18.04,82.05 RY8.2 RY4.2 RY5.2
HDMI_HPD: length 12.8
  TOP w0.102: QY1.2 15.6,94.35 15.52,94.26 RY10.1 15.52,93.54 15.27,93.3 15.02,93.3 14.64,92.92 CY10.2 14.64,92.82 v3(15.53,92.82)
  BOTTOM w0.102: v3(15.53,92.82) 15.53,92.82 15.68,92.67 16.82,92.67 17,92.49 v2(17,92.2) 17,91.96 16.84,91.8 DY1.7 DY1.4 14.51,91.8 13.62,92.69 13.62,92.94 12.92,93.63 11.95,93.63 11.59,93.28 JHDMI1.19
HDMI_HPD#: length 107.9
  TOP w0.102: v3(13.87,96.65) RY2.2 13.87,95.66 14.95,96.73 QY1.6
  IN2 w0.127: v3(75.18,75.83) 75.1,75.75 74.26,75.75 73.52,76.49 71.32,76.49 70.37,77.44 64.7,77.44 63.85,76.59 57.1,76.59 v3(56.79,76.27)
  BOTTOM w0.102: UC4.D27 99.29,77.44 99.29,76.83 99.1,76.64 98.84,76.64 98.69,76.79 98.47,76.79 98.3,76.62 98.15,76.62 97.87,76.9 96.81,76.9 96.26,76.35 90.75,76.35 90.21,75.81 v2(87.08,75.81) 86.98,75.7 75.3,75.7 v3(75.18,75.83) ; v3(56.79,76.27) 56.27,76.79 53.12,76.79 50.38,74.05 45.32,74.05 44.59,74.78 40.15,74.78 39.84,75.09 35.63,75.09 30.84,79.88 30.84,87.81 30.3,88.35 30.3,91.54 27.72,94.12 24.41,94.12 23.68,94.85 20.48,94.85 19.04,96.3 16.57,96.3 16.21,96.65 v3(13.87,96.65)
HDMI_R_CK+: length 11.1
  IN2 w0.127: JHDMI1.10 12.97,89.25 13.41,89.25 14.65,88.01 14.65,86.86 v3(14.49,86.7)
  BOTTOM w0.102: v3(14.49,86.7) 14.66,86.87 14.66,87.12 14.92,87.37 15.53,87.37 15.68,87.22 15.7,87.22 16.07,86.85 16.07,86.83 16.16,86.74 16.28,86.74 16.41,86.87 DY2.9 DY2.1 18.02,86.87 18.12,86.77 18.32,86.77 RY12.2 19.1,86.75 19.3,86.75 19.44,86.9 LY1.2 20.11,87.07 RY11.2
HDMI_R_CK-: length 11.1
  IN2 w0.127: v3(15.08,86.7) 14.92,86.86 14.92,88.12 13.52,89.52 12.76,89.52 JHDMI1.12
  BOTTOM w0.102: RY13.2 20.11,86.22 LY1.3 19.44,86.4 19.3,86.54 19,86.54 RY12.1 18.38,86.56 18.19,86.56 18.01,86.37 DY2.2 DY2.8 16.39,86.37 16.24,86.52 16.07,86.52 v4(15.78,86.81) 15.44,87.16 15.01,87.16 14.88,87.03 14.88,86.9 v3(15.08,86.7)
HDMI_R_D0+: length 14.2
  IN2 w0.127: JHDMI1.7 11.42,87.28 11.63,87.06 11.63,84.15 12.5,83.28 15.05,83.28 15.2,83.13 v3(15.2,82.8)
  BOTTOM w0.102: v3(15.2,82.8) 15.53,83.14 15.71,83.14 15.8,83.04 15.8,82.6 16.07,82.33 16.4,82.33 16.55,82.19 DY3.8 DY3.2 18.06,82.19 18.34,82.47 18.51,82.47 RY15.2 19.16,82.48 19.28,82.48 19.38,82.38 19.65,82.38 19.8,82.22 LY2.3
HDMI_R_D0-: length 14.2
  IN2 w0.127: JHDMI1.9 11.55,87.68 11.55,87.53 11.9,87.18 11.9,84.26 12.61,83.54 15.06,83.54 v3(15.2,83.68)
  BOTTOM w0.102: v3(15.2,83.68) 15.53,83.35 15.8,83.35 16.02,83.13 16.02,82.69 16.16,82.55 16.35,82.55 16.49,82.69 DY3.9 DY3.1 18.45,82.69 RY15.1 19.2,82.69 19.37,82.69 19.47,82.59 19.66,82.59 19.79,82.72 LY2.2
HDMI_R_D1+: length 10.3
  IN2 w0.127: v3(14.95,85.38) 14.78,85.21 14.78,84.96 14.42,84.6 13.93,84.6 13.39,85.14 13.39,85.88 13.15,86.12 12.84,86.12 JHDMI1.4
  BOTTOM w0.102: v3(14.95,85.38) 14.77,85.2 14.77,85.04 14.89,84.91 15.53,84.91 v4(15.69,85.07) 15.85,85.23 16.28,85.23 16.42,85.37 DY2.7 DY2.4 17.94,85.37 18.12,85.19 18.51,85.19 RY18.2 19.21,84.87 19.31,84.87 19.4,84.96 LY3.2
HDMI_R_D1-: length 10.3
  IN2 w0.127: v3(14.36,85.38) 14.51,85.24 14.51,85.07 14.31,84.87 14.04,84.87 13.66,85.25 13.66,85.99 13.26,86.39 12.89,86.39 JHDMI1.6
  BOTTOM w0.102: v3(14.36,85.38) 14.55,85.2 14.55,84.95 14.8,84.69 15.63,84.69 15.96,85.02 16.28,85.02 16.43,84.87 DY2.6 DY2.5 18,84.87 18.1,84.97 18.19,84.97 RY18.1 18.89,84.65 19.4,84.65 19.58,84.46 LY3.3
HDMI_R_D2+: length 11.6
  BOTTOM w0.102: JHDMI1.1 11.23,84.57 11.62,84.57 11.7,84.48 11.7,84.17 14.01,81.86 14.01,81.84 14.39,81.47 14.41,81.47 14.7,81.17 15.18,81.17 15.57,80.79 v4(15.91,80.79) 16.35,80.79 16.46,80.69 DY3.6 DY3.5 18.18,80.69 18.29,80.8 18.4,80.8 RY21.2 19.18,80.72 19.29,80.72 19.7,80.31 LY4.3
HDMI_R_D2-: length 11.5
  BOTTOM w0.102: LY4.2 19.51,80.81 19.38,80.94 19.18,80.94 RY21.1 18.56,81.02 18.29,81.02 18.12,81.19 DY3.4 DY3.7 16.58,81.19 16.43,81.03 15.63,81.03 15.27,81.39 14.79,81.39 v4(14.36,81.82) 14.04,82.15 12.98,83.2 11.92,84.26 11.92,84.57 11.71,84.78 11.45,84.78 JHDMI1.3
HDMI_SCLK: length 19.2
  TOP w0.102: v3(15.8,89.49) 15.8,89.78 17.07,91.04 18.15,91.04 18.47,91.37 18.47,92.87 18.07,93.28 18.07,93.55 v2(18.16,93.65) 18.17,93.65 QY2.1
  BOTTOM w0.102: RPY1.8 17.05,88.88 16.5,89.43 15.87,89.43 v3(15.8,89.49) 15.8,89.64 16.17,90.01 16.17,90.65 16.02,90.8 DY1.8 DY1.2 14.29,90.8 13.37,91.73 13.37,92.87 12.83,93.4 12.1,93.4 11.72,93.02 11.72,92.05 JHDMI1.15
HDMI_SDATA: length 14.4
  TOP w0.102: QY3.1 18.7,91.27 18.24,90.81 17.16,90.81 16.31,89.96 v3(16.31,88.81) 15.66,88.81 v2(15.5,88.96)
  BOTTOM w0.102: JHDMI1.16 12.99,91.78 14.47,90.3 DY1.1 DY1.9 15.73,90.3 15.83,90.2 15.83,90.1 15.32,89.59 15.32,89.29 15.81,88.81 v3(16.31,88.81) 16.53,88.59 16.53,88.08 16.72,87.89 17.31,87.89 17.55,88.14 RPY1.7
HDMI_TX0+: length 108.9
  IN2 w0.127: v3(113.32,96.05) 113.18,95.9 113.18,95.9 113.18,93.9 112.35,93.07 110.13,93.07 109.81,92.75 107.65,92.75 106.91,93.49 105.38,93.49 100.5,98.38 86.39,98.38 84.92,96.91 42.28,96.91 39.35,93.99 38.97,93.99 37.47,92.49 37.47,91.73 28.46,82.71 26.97,82.71 v3(26.86,82.6)
  BOTTOM w0.089: UC4.AR3 114.64,89.95 114.79,90.1 114.79,90.43 114.55,90.67 114.55,91 113.62,91.93 113.62,92.12 113.63,92.13 113.63,92.16
  BOTTOM w0.102: v3(113.32,96.05) 113.13,95.86 113.13,95.58 113.63,95.07 113.63,92.16 ; CY6.2 24.52,82.41 25.79,82.41 26.17,82.79 26.68,82.79 v3(26.86,82.6)
HDMI_TX0-: length 108.8
  IN2 w0.127: v3(26.86,83.37) 26.86,83.2 27.08,82.98 28.35,82.98 37.21,91.84 37.21,92.6 38.86,94.26 39.24,94.26 42.17,97.18 84.81,97.18 86.28,98.65 100.61,98.65 105.49,93.76 107.02,93.76 107.76,93.02 109.7,93.02 110.02,93.34 112.24,93.34 112.91,94.01 112.91,95.84 112.66,96.1 v3(112.34,96.1)
  BOTTOM w0.089: 113.42,92.16 113.42,92.15 113.43,92.13 113.43,91.85 114.36,90.93 114.36,90.6 114.51,90.44 UC4.AR1
  BOTTOM w0.102: v3(26.86,83.37) 26.86,83.12 26.74,83 26.08,83 25.7,82.62 24.5,82.62 CY5.2 ; 113.42,92.16 113.42,94.98 112.91,95.49 112.91,95.94 112.76,96.1 v3(112.34,96.1)
HDMI_TX1+: length 115.8
  IN2 w0.127: v3(112.98,96.94) 112.98,97.34 112.85,97.47 112.41,97.47 112.03,97.84 112.03,98.14 111.45,98.73 107.92,98.73 105.88,100.77 85.4,100.77 83.86,99.23 79.73,99.23 78.72,100.25 75.4,100.25 74.46,99.3 71.44,99.3 70.49,100.25 38.45,100.25 34.29,96.08 28.85,96.08 23.71,90.94 23.71,85.71 24.71,84.71 24.96,84.71 25.09,84.83 v3(25.09,85.44)
  BOTTOM w0.102: v3(112.98,96.94) 112.98,97.34 113.14,97.49 113.45,97.49 114.12,96.83 114.12,92.14 114.9,91.35 114.9,90.65 114.99,90.57 114.99,89.89 UC4.AT2 ; v3(25.09,85.44) 25.09,84.89 24.93,84.74 24.22,84.74 24.11,84.85 CY2.2
HDMI_TX1-: length 115.8
  IN2 w0.127: v3(25.16,84.32) 25.04,84.44 24.6,84.44 23.44,85.6 23.44,91.05 28.74,96.35 34.18,96.35 38.34,100.51 70.6,100.51 71.55,99.56 74.34,99.56 75.29,100.51 78.83,100.51 79.84,99.5 83.75,99.5 85.29,101.03 105.99,101.03 108.03,98.99 111.56,98.99 112.3,98.25 112.3,97.95 112.52,97.74 112.85,97.74 v3(112.99,97.87)
  BOTTOM w0.102: UC4.AT3 115.13,89.6 115.29,89.76 115.29,90.01 115.25,90.05 115.25,90.06 115.2,90.1 115.2,90.66 115.12,90.74 115.12,91.44 114.33,92.23 114.33,96.92 113.54,97.71 113.15,97.71 v3(112.99,97.87) ; v3(25.16,84.32) 24.96,84.52 24.35,84.52 CY1.2
HDMI_TX2+: length 121.1
  IN2 w0.127: v3(106.52,97.85) 106.66,97.99 106.66,98.84 105.57,99.93 85.67,99.93 84.2,98.46 79.41,98.46 78.41,99.46 75.75,99.46 74.78,98.48 70.98,98.48 70,99.46 41.11,99.46 36.28,94.62 28.49,94.62 24.52,90.65 24.52,87.54 26.17,85.89 26.17,80.85 25.78,80.46 25.45,80.46 v3(25.3,80.32)
  BOTTOM w0.102: v3(25.3,80.32) 25.1,80.51 24.59,80.51 CY4.2 ; v3(106.52,97.85) 106.7,98.03 106.7,98.32 107.23,98.85 113.94,98.85 115.05,97.74 115.05,92.53 116.31,91.27 116.31,90.57 116.13,90.39 116.13,90.34 116.13,90.15 116.26,90.02 116.26,89.76 116.09,89.59 UC4.AV3
HDMI_TX2-: length 121.1
  IN2 w0.127: v3(107.47,97.85) 107.04,97.85 106.93,97.96 106.93,98.95 105.68,100.2 85.56,100.2 84.09,98.73 79.52,98.73 78.52,99.73 75.64,99.73 74.67,98.75 71.09,98.75 70.11,99.73 41,99.73 36.16,94.89 28.38,94.89 24.25,90.76 24.25,87.43 25.9,85.78 25.9,80.96 25.67,80.73 25.5,80.73 25.3,80.93 v3(25.3,81.08)
  BOTTOM w0.102: CY3.2 24.4,80.73 25.12,80.73 25.3,80.91 v3(25.3,81.08) ; UC4.AV2 115.91,89.93 115.91,90.25 115.91,90.48 116.1,90.66 116.1,91.18 114.83,92.44 114.83,97.65 113.85,98.63 107.32,98.63 106.92,98.23 106.92,97.98 107.04,97.85 v3(107.47,97.85)
HGNDA: length 24.5
  TOP w1.016: RA18.2 17.53,26.4 17.53,26.12 16.9,25.49 16.9,24.79 14.97,22.86 v2(14.97,21.9) 14.97,20.79 13.7,19.52 DA3.3 13.7,17.2 13.11,16.62 CA14.1 11.08,17.38 8.26,17.38 4.6,13.72 JHP1.5
HGNDB: length 8.7
  TOP w1.016: 15.91,16.32 15.91,17.59 15.63,17.87 DA3.2 16.14,18.79 16.14,22.41 17.15,23.43 17.74,23.43 RA17.2
  vias: v3(15.04,13.83) v3(15.63,13.83)
HP_OUTL: length 12
  TOP w0.203: RA25.2 26.3,17.76 RA19.1 26.7,18.86 v3(26.7,19.14) 26.7,19.16 25.37,20.49 UA1.32
  BOTTOM w0.203: v3(26.7,19.14) 26.35,19.14 25.59,19.9 23.07,19.9 22.64,20.33 v2(21.95,20.33) 20.99,20.33 20.48,20.84 CA23.1
HP_OUTR: length 14.2
  TOP w0.203: UA1.33 25.77,20.56 26.74,19.59 26.91,19.59 27.82,18.68 v3(27.82,18.04)
  BOTTOM w0.203: CA24.1 19.21,20.84 20.48,19.57 22.44,19.57 22.75,19.25 24.99,19.25 v2(25.13,19.11) 26.2,18.04 RA29.2 RA20.1 v3(27.82,18.04)
HPOUT_L: length 17.3
  TOP w0.203: v3(27.84,15.88) 27.85,15.88 27.85,16.01 RA22.2 27.05,16.81 RA19.2
  IN2 w0.203: v3(17.2,21.54) 18.45,21.54 20.4,19.59 23.09,19.59 23.51,19.18 24.91,19.18 26.14,17.94 26.14,17.49 27.74,15.88 v3(27.84,15.88)
  BOTTOM w0.203: CA17.1 RA8.1 16.42,21.32 16.64,21.54 v3(17.2,21.54)
HPOUT_L1: length 14.4
  BOTTOM w0.203: JHP1.4 7.6,15.83 v2(8.78,17.01) 9.26,17.48 11.51,17.48 12.68,16.32 14.69,16.32 DA5.3 16.16,17.79 16.16,19.92 RA8.2
HPOUT_R: length 18.7
  TOP w0.203: RA23.2 28.48,16.67 28.08,16.67 v3(27.84,16.91)
  IN2 w0.203: v3(27.84,16.91) 27.84,17.19 25.19,19.84 23.78,19.84 23.37,20.25 20.68,20.25 18.42,22.51 v3(17.53,22.51)
  BOTTOM w0.203: RA9.1 CA19.1 15.15,21.6 16.23,21.6 16.61,21.98 17,21.98 v3(17.53,22.51) ; RA20.2 27.62,17.13 v3(27.84,16.91)
HPOUT_R1: length 7.2
  BOTTOM w0.203: RA9.2 15.07,18.86 DA5.2 14.94,18.5 13.18,18.5 12.49,19.19 v1(12.17,19.19) 11.61,19.19 JHP1.1
HSIC_RCOMP: length 9.4
  BOTTOM w0.254: UC4.A7 96.71,88.32 96.71,93.49 RC64.2 97.75,94.52 97.75,95.41 v2(97.92,95.59)
HUB_BUSJ: length 4.2
  TOP w0.102: US2.18 193.1,57.57 v1(192.6,57.07) 192.13,56.6 191.63,56.6 191.05,56.03 191.05,55.83 RS13.2
HUB_OVCJ: length 4.6
  TOP w0.102: US2.1 199.14,57.57 CS11.1 199.93,56.78 201.3,56.78 RS10.2
HUB_VBUSM: length 5.1
  TOP w0.102: RS14.2 190.3,56.42 CS12.2 190.7,56.22 191.26,56.78 v1(191.26,57.18) 191.57,57.49 192.34,57.49 192.91,58.07 US2.17
HUB_XIN: length 4.9
  TOP w0.102: US2.4 198.41,59.07 198.99,59.65 201.28,59.65 YS1.1
HUB_XOUT: length 2.3
  TOP w0.102: US2.3 198.84,58.57 199.13,58.86 YS1.3
HUB_XRSTJ: length 3.6
  TOP w0.102: RS12.2 192.06,57.98 v1(192.53,58.44) 192.65,58.57 US2.16
ICLK_ICOMP: length 4.6
  TOP w0.102: v3(108.8,84.03) 108.8,84.24 109.28,84.72 109.28,86.34 109.13,86.49 v2(109.13,86.5)
  TOP w0.254: v3(108.8,84.03) 108.8,83.5 108.24,82.94 RC30.2
  BOTTOM w0.254: v3(108.8,84.03) 109.18,83.66 UC4.AD14
